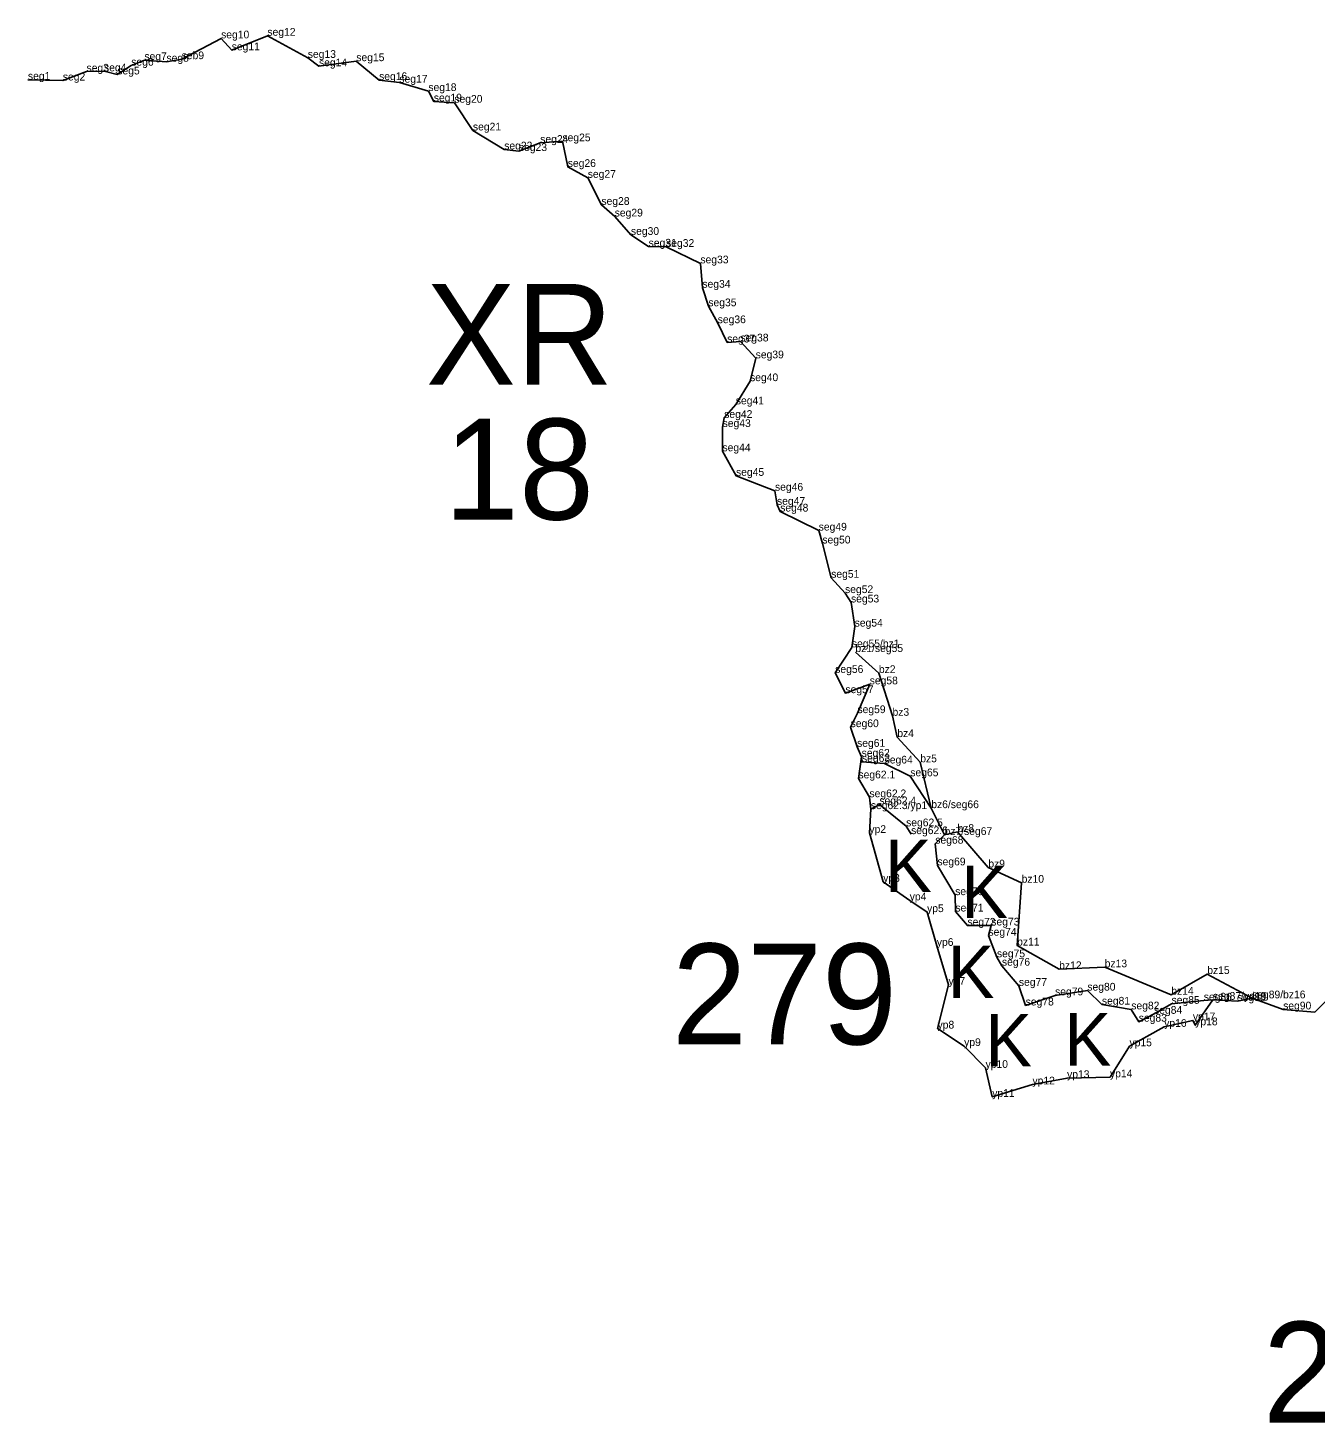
# Model space of a CAD drawing. Extents: x 2072529 to 2268796, y 436423 to 470406.
# Drawn here: x 2240745 to 2241579, y 439812 to 440717 of the extents above; entities that cross this region are included whole.
import ezdxf

# ---------------------------------------------------------------- set-up
doc = ezdxf.new("R2010")
doc.units = 0
for name, color, linetype in [('Default', 7, 'Continuous'), ('Exist Environmental Wetland Boundary Cogo Comment', 7, 'Continuous'), ('Exist Environmental Wetland Boundary Cogo Point CELL', 7, 'Continuous'), ('Exist Hydro Jurisdictional Stream or Body of Water NEU Mitigable Cogo Comment', 7, 'Continuous'), ('Old_Level_20', 7, 'Continuous'), ('Old_Level_52', 7, 'Continuous')]:
    doc.layers.add(name, color=color, linetype=linetype)

msp = doc.modelspace()

# ---------------------------------------------------------------- linework, layer by layer
at = {"layer": 'Old_Level_20'}
for p, q in [((2240900.59, 440712.1), (2240900.59, 440712.1)), ((2240870.61, 440710.41), (2240870.61, 440710.41)), ((2240877.46, 440702.68), (2240877.46, 440702.68)), ((2240812.4, 440692.72), (2240812.4, 440692.72)), ((2240820.91, 440696.34), (2240820.91, 440696.34)), ((2240835.21, 440695.28), (2240835.21, 440695.28)), ((2240845.05, 440696.92), (2240845.05, 440696.92)), ((2240926.76, 440697.76), (2240926.76, 440697.76)), ((2240958.18, 440695.63), (2240958.18, 440695.63)), ((2240745.46, 440683.58), (2240745.46, 440683.58)), ((2240783.43, 440688.86), (2240783.43, 440688.86)), ((2240794.77, 440689.05), (2240794.77, 440689.05)), ((2240803.35, 440687.04), (2240803.35, 440687.04)), ((2240934.01, 440692.29), (2240934.01, 440692.29)), ((2240768.08, 440683.09), (2240768.08, 440683.09)), ((2240972.96, 440683.39), (2240972.96, 440683.39)), ((2240986.1, 440681.7), (2240986.1, 440681.7)), ((2241004.88, 440676.28), (2241004.88, 440676.28)), ((2241008.39, 440669.53), (2241008.39, 440669.53)), ((2241021.69, 440668.7), (2241021.69, 440668.7)), ((2241033.73, 440650.71), (2241033.73, 440650.71)), ((2241054, 440638.41), (2241054, 440638.41)), ((2241077.34, 440642.67), (2241077.34, 440642.67)), ((2241091.72, 440643.72), (2241091.72, 440643.72)), ((2241063.51, 440637.41), (2241063.51, 440637.41)), ((2241095.19, 440627.08), (2241095.19, 440627.08)), ((2241108.12, 440620.04), (2241108.12, 440620.04)), ((2241116.98, 440602.51), (2241116.98, 440602.51)), ((2241125.58, 440594.97), (2241125.58, 440594.97)), ((2241136.1, 440583.04), (2241136.1, 440583.04)), ((2241147.55, 440575.46), (2241147.55, 440575.46)), ((2241158.87, 440575.28), (2241158.87, 440575.28)), ((2241181.1, 440564.6), (2241181.1, 440564.6)), ((2241182.39, 440548.78), (2241182.39, 440548.78)), ((2241186.24, 440536.8), (2241186.24, 440536.8)), ((2241192.31, 440525.82), (2241192.31, 440525.82)), ((2241198.43, 440513.33), (2241198.43, 440513.33)), ((2241207.02, 440513.98), (2241207.02, 440513.98)), ((2241216.9, 440503.05), (2241216.9, 440503.05)), ((2241213.27, 440488.25), (2241213.27, 440488.25)), ((2241204.04, 440473.22), (2241204.04, 440473.22)), ((2241195.49, 440458.54), (2241195.49, 440458.54)), ((2241196.53, 440464.43), (2241196.53, 440464.43)), ((2241195.39, 440442.82), (2241195.39, 440442.82)), ((2241204.17, 440426.87), (2241204.17, 440426.87)), ((2241229.41, 440417.26), (2241229.41, 440417.26)), ((2241230.72, 440408.11), (2241230.72, 440408.11)), ((2241232.79, 440403.75), (2241232.79, 440403.75)), ((2241257.72, 440391.43), (2241257.72, 440391.43)), ((2241260.12, 440383.05), (2241260.12, 440383.05)), ((2241265.82, 440360.85), (2241265.82, 440360.85)), ((2241274.8, 440350.9), (2241274.8, 440350.9)), ((2241278.67, 440344.84), (2241278.67, 440344.84)), ((2241281.02, 440329.2), (2241281.02, 440329.2)), ((2241279.21, 440315.74), (2241279.21, 440315.74)), ((2241281.51, 440312.72), (2241281.51, 440312.72)), ((2241268.43, 440299.17), (2241268.43, 440299.17)), ((2241296.71, 440299.1), (2241296.71, 440299.1)), ((2241275.06, 440286.05), (2241275.06, 440286.05)), ((2241290.77, 440291.78), (2241290.77, 440291.78)), ((2241282.83, 440273.11), (2241282.83, 440273.11)), ((2241305.55, 440271.4), (2241305.55, 440271.4)), ((2241278.42, 440264.03), (2241278.42, 440264.03)), ((2241282.59, 440251.27), (2241282.59, 440251.27)), ((2241308.65, 440257.59), (2241308.65, 440257.59)), ((2241285.54, 440244.89), (2241285.54, 440244.89)), ((2241285.76, 440241.46), (2241285.76, 440241.46)), ((2241300.42, 440240.47), (2241300.42, 440240.47)), ((2241323.52, 440241.26), (2241323.52, 440241.26)), ((2241317.07, 440232.2), (2241317.07, 440232.2)), ((2241283.48, 440230.81), (2241283.48, 440230.81)), ((2241290.61, 440218.6), (2241290.61, 440218.6)), ((2241297.04, 440213.96), (2241297.04, 440213.96)), ((2241291.52, 440210.9), (2241291.52, 440210.9)), ((2241330.65, 440211.53), (2241330.65, 440211.53)), ((2241330.65, 440211.53), (2241330.65, 440211.53)), ((2241290.57, 440195.44), (2241290.57, 440195.44)), ((2241314.36, 440199.77), (2241314.36, 440199.77)), ((2241347.6, 440196.12), (2241347.6, 440196.12)), ((2241317.58, 440194.69), (2241317.58, 440194.69)), ((2241333.25, 440188.5), (2241333.25, 440188.5)), ((2241339.26, 440194.15), (2241339.26, 440194.15)), ((2241339.26, 440194.15), (2241339.26, 440194.15)), ((2241334.64, 440174.46), (2241334.64, 440174.46)), ((2241367.6, 440173.08), (2241367.6, 440173.08)), ((2241299.52, 440163.78), (2241299.52, 440163.78)), ((2241389.18, 440163.21), (2241389.18, 440163.21)), ((2241316.69, 440151.78), (2241316.69, 440151.78)), ((2241346.14, 440155.15), (2241346.14, 440155.15)), ((2241327.93, 440144.15), (2241327.93, 440144.15)), ((2241346.29, 440144.54), (2241346.29, 440144.54)), ((2241354.1, 440135.38), (2241354.1, 440135.38)), ((2241369.55, 440135.48), (2241369.55, 440135.48)), ((2241367.69, 440128.9), (2241367.69, 440128.9)), ((2241334.25, 440122.27), (2241334.25, 440122.27)), ((2241373.19, 440114.85), (2241373.19, 440114.85)), ((2241386.29, 440122.5), (2241386.29, 440122.5)), ((2241376.42, 440109.43), (2241376.42, 440109.43)), ((2241413.51, 440107.19), (2241413.51, 440107.19)), ((2241442.98, 440108.39), (2241442.98, 440108.39)), ((2241341.85, 440097.04), (2241341.85, 440097.04)), ((2241387.41, 440096.36), (2241387.41, 440096.36)), ((2241509.42, 440104.04), (2241509.42, 440104.04)), ((2241410.86, 440090.21), (2241410.86, 440090.21)), ((2241431.76, 440093.29), (2241431.76, 440093.29)), ((2241486.13, 440090.61), (2241486.13, 440090.61)), ((2241507.18, 440086.84), (2241507.18, 440086.84)), ((2241513.12, 440087.33), (2241513.12, 440087.33)), ((2241513.12, 440087.33), (2241513.12, 440087.33)), ((2241529.06, 440086.49), (2241529.06, 440086.49)), ((2241538.49, 440088.28), (2241538.49, 440088.28)), ((2241538.49, 440088.28), (2241538.49, 440088.28)), ((2241391.79, 440083.64), (2241391.79, 440083.64)), ((2241441.19, 440084.2), (2241441.19, 440084.2)), ((2241460.21, 440081.1), (2241460.21, 440081.1)), ((2241474.98, 440078.25), (2241474.98, 440078.25)), ((2241486.3, 440084.74), (2241486.3, 440084.74)), ((2241558.6, 440081.08), (2241558.6, 440081.08)), ((2241579.17, 440079.38), (2241579.17, 440079.38)), ((2241334.73, 440068.7), (2241334.73, 440068.7)), ((2241465.06, 440073.15), (2241465.06, 440073.15)), ((2241481.53, 440069.8), (2241481.53, 440069.8)), ((2241500.12, 440074), (2241500.12, 440074)), ((2241501.66, 440070.84), (2241501.66, 440070.84)), ((2241351.94, 440057.37), (2241351.94, 440057.37)), ((2241459.06, 440057.21), (2241459.06, 440057.21)), ((2241365.82, 440043.17), (2241365.82, 440043.17)), ((2241396.19, 440032.47), (2241396.19, 440032.47)), ((2241418.63, 440036.6), (2241418.63, 440036.6)), ((2241446.44, 440037.09), (2241446.44, 440037.09)), ((2241370.15, 440024.41), (2241370.15, 440024.41))]:
    msp.add_line(p, q, dxfattribs=at)
for points in [[(2241281.51, 440312.72), (2241296.71, 440299.1), (2241305.55, 440271.4), (2241308.65, 440257.59), (2241323.52, 440241.26), (2241330.65, 440211.53)], [(2241513.12, 440087.33), (2241501.66, 440070.84), (2241500.12, 440074), (2241481.53, 440069.8), (2241459.06, 440057.21), (2241446.44, 440037.09), (2241418.63, 440036.6), (2241396.19, 440032.47), (2241370.15, 440024.41), (2241365.82, 440043.17), (2241351.94, 440057.37), (2241334.73, 440068.7), (2241341.85, 440097.04), (2241334.25, 440122.27), (2241327.93, 440144.15), (2241316.69, 440151.78), (2241299.52, 440163.78), (2241290.57, 440195.44), (2241291.52, 440210.9)], [(2241339.26, 440194.15), (2241347.6, 440196.12), (2241367.6, 440173.08), (2241389.18, 440163.21), (2241386.29, 440122.5), (2241413.51, 440107.19), (2241442.98, 440108.39), (2241486.13, 440090.61), (2241509.42, 440104.04), (2241538.49, 440088.28)]]:
    msp.add_lwpolyline(points, dxfattribs=at)
at = {"layer": 'Old_Level_52'}
for points in [[(2240745.46, 440683.58), (2240768.08, 440683.09), (2240783.43, 440688.86), (2240794.77, 440689.05), (2240803.35, 440687.04), (2240812.4, 440692.72), (2240820.91, 440696.34), (2240835.21, 440695.28), (2240845.05, 440696.92), (2240870.61, 440710.41), (2240877.46, 440702.68), (2240900.59, 440712.1), (2240926.76, 440697.76), (2240934.01, 440692.29), (2240958.18, 440695.63), (2240972.96, 440683.39), (2240986.1, 440681.7), (2241004.88, 440676.28), (2241008.39, 440669.53), (2241021.69, 440668.7)], [(2241021.69, 440668.7), (2241033.73, 440650.71), (2241054, 440638.41), (2241063.51, 440637.41), (2241077.34, 440642.67), (2241091.72, 440643.72), (2241095.19, 440627.08), (2241108.12, 440620.04), (2241116.98, 440602.51), (2241125.58, 440594.97), (2241136.1, 440583.04), (2241147.55, 440575.46), (2241158.87, 440575.28), (2241181.1, 440564.6), (2241182.39, 440548.78), (2241186.24, 440536.8), (2241192.31, 440525.82), (2241198.43, 440513.33), (2241207.02, 440513.98), (2241216.9, 440503.05), (2241213.27, 440488.25), (2241204.04, 440473.22), (2241196.53, 440464.43), (2241195.49, 440458.54), (2241195.39, 440442.82), (2241204.17, 440426.87), (2241229.41, 440417.26), (2241230.72, 440408.11), (2241232.79, 440403.75), (2241257.72, 440391.43), (2241260.12, 440383.05), (2241265.82, 440360.85), (2241274.8, 440350.9), (2241278.67, 440344.84), (2241281.02, 440329.2), (2241279.21, 440315.74), (2241268.43, 440299.17), (2241275.06, 440286.05), (2241290.77, 440291.78), (2241282.83, 440273.11), (2241278.42, 440264.03), (2241282.59, 440251.27), (2241285.54, 440244.89), (2241285.76, 440241.46)], [(2241285.54, 440244.89), (2241283.48, 440230.81), (2241290.61, 440218.6), (2241291.52, 440210.9), (2241297.04, 440213.96), (2241314.36, 440199.77), (2241317.58, 440194.69)], [(2241285.76, 440241.46), (2241300.42, 440240.47), (2241317.07, 440232.2), (2241330.65, 440211.53), (2241339.26, 440194.15), (2241333.25, 440188.5), (2241334.64, 440174.46), (2241346.14, 440155.15), (2241346.29, 440144.54), (2241354.1, 440135.38), (2241369.55, 440135.48), (2241367.69, 440128.9), (2241373.19, 440114.85), (2241376.42, 440109.43), (2241387.41, 440096.36), (2241391.79, 440083.64), (2241410.86, 440090.21), (2241431.76, 440093.29), (2241441.19, 440084.2), (2241460.21, 440081.1), (2241465.06, 440073.15), (2241474.98, 440078.25), (2241486.3, 440084.74), (2241507.18, 440086.84), (2241513.12, 440087.33), (2241529.06, 440086.49), (2241538.49, 440088.28), (2241558.6, 440081.08), (2241579.17, 440079.38), (2241588.56, 440088.74)]]:
    msp.add_lwpolyline(points, dxfattribs=at)

# ---------------------------------------------------------------- texts
at = {"layer": 'Default'}
for s, p in [('XR', (2241003.21, 440485.96)), ('18', (2241015, 440398.56)), ('279', (2241162.66, 440058.41)), ('281', (2241545.45, 439813.28))]:
    msp.add_text(s, height=65.34, dxfattribs=at).set_placement(p)
at = {"layer": 'Exist Environmental Wetland Boundary Cogo Comment'}
for s, p in [('bz1/seg55', (2241281.51, 440312.72)), ('bz2', (2241296.71, 440299.1)), ('bz3', (2241305.55, 440271.4)), ('bz4', (2241308.65, 440257.59)), ('bz5', (2241323.52, 440241.26)), ('bz6/seg66', (2241330.65, 440211.53)), ('yp2', (2241290.57, 440195.44)), ('bz8', (2241347.6, 440196.12)), ('bz9', (2241367.6, 440173.08)), ('yp3', (2241299.52, 440163.78)), ('bz10', (2241389.18, 440163.21)), ('yp4', (2241316.69, 440151.78)), ('yp5', (2241327.93, 440144.15)), ('yp6', (2241334.25, 440122.27)), ('bz11', (2241386.29, 440122.5)), ('bz13', (2241442.98, 440108.39)), ('bz12', (2241413.51, 440107.19)), ('bz15', (2241509.42, 440104.04)), ('yp7', (2241341.85, 440097.04)), ('bz14', (2241486.13, 440090.61)), ('yp17', (2241500.12, 440074)), ('yp8', (2241334.73, 440068.7)), ('yp16', (2241481.53, 440069.8)), ('yp18', (2241501.66, 440070.84)), ('yp9', (2241351.94, 440057.37)), ('yp15', (2241459.06, 440057.21)), ('yp10', (2241365.82, 440043.17)), ('yp13', (2241418.63, 440036.6)), ('yp14', (2241446.44, 440037.09)), ('yp12', (2241396.19, 440032.47)), ('yp11', (2241370.15, 440024.41))]:
    msp.add_text(s, height=5, dxfattribs=at).set_placement(p)
at = {"layer": 'Exist Environmental Wetland Boundary Cogo Point CELL'}
for p in [(2241300.62, 440157.2), (2241349.98, 440140.33), (2241341.23, 440088.47), (2241365.6, 440044.11), (2241416.83, 440044.74)]:
    msp.add_text('K', height=34, dxfattribs=at).set_placement(p)
at = {"layer": 'Exist Hydro Jurisdictional Stream or Body of Water NEU Mitigable Cogo Comment'}
for s, p in [('seg10', (2240870.61, 440710.41)), ('seg12', (2240900.59, 440712.1)), ('seb9', (2240845.05, 440696.92)), ('seg11', (2240877.46, 440702.68)), ('seg13', (2240926.76, 440697.76)), ('seg3', (2240783.43, 440688.86)), ('seg4', (2240794.77, 440689.05)), ('seg6', (2240812.4, 440692.72)), ('seg7', (2240820.91, 440696.34)), ('seg8', (2240835.21, 440695.28)), ('seg14', (2240934.01, 440692.29)), ('seg15', (2240958.18, 440695.63)), ('seg1', (2240745.46, 440683.58)), ('seg2', (2240768.08, 440683.09)), ('seg5', (2240803.35, 440687.04)), ('seg16', (2240972.96, 440683.39)), ('seg17', (2240986.1, 440681.7)), ('seg18', (2241004.88, 440676.28)), ('seg19', (2241008.39, 440669.53)), ('seg20', (2241021.69, 440668.7)), ('seg21', (2241033.73, 440650.71)), ('seg24', (2241077.34, 440642.67)), ('seg25', (2241091.72, 440643.72)), ('seg22', (2241054, 440638.41)), ('seg23', (2241063.51, 440637.41)), ('seg26', (2241095.19, 440627.08)), ('seg27', (2241108.12, 440620.04)), ('seg28', (2241116.98, 440602.51)), ('seg29', (2241125.58, 440594.97)), ('seg30', (2241136.1, 440583.04)), ('seg31', (2241147.55, 440575.46)), ('seg32', (2241158.87, 440575.28)), ('seg33', (2241181.1, 440564.6)), ('seg34', (2241182.39, 440548.78)), ('seg35', (2241186.24, 440536.8)), ('seg36', (2241192.31, 440525.82)), ('seg37', (2241198.43, 440513.33)), ('seg38', (2241207.02, 440513.98)), ('seg39', (2241216.9, 440503.05)), ('seg40', (2241213.27, 440488.25)), ('seg41', (2241204.04, 440473.22)), ('seg42', (2241196.53, 440464.43)), ('seg43', (2241195.49, 440458.54)), ('seg44', (2241195.39, 440442.82)), ('seg45', (2241204.17, 440426.87)), ('seg46', (2241229.41, 440417.26)), ('seg47', (2241230.72, 440408.11)), ('seg48', (2241232.79, 440403.75)), ('seg49', (2241257.72, 440391.43)), ('seg50', (2241260.12, 440383.05)), ('seg51', (2241265.82, 440360.85)), ('seg52', (2241274.8, 440350.9)), ('seg53', (2241278.67, 440344.84)), ('seg54', (2241281.02, 440329.2)), ('seg55/bz1', (2241279.21, 440315.74)), ('seg56', (2241268.43, 440299.17)), ('seg58', (2241290.77, 440291.78)), ('seg57', (2241275.06, 440286.05)), ('seg59', (2241282.83, 440273.11)), ('seg60', (2241278.42, 440264.03)), ('seg61', (2241282.59, 440251.27)), ('seg62', (2241285.54, 440244.89)), ('seg63', (2241285.76, 440241.46)), ('seg64', (2241300.42, 440240.47)), ('seg62.1', (2241283.48, 440230.81)), ('seg65', (2241317.07, 440232.2)), ('seg62.2', (2241290.61, 440218.6)), ('seg62.3/yp1', (2241291.52, 440210.9)), ('seg62.4', (2241297.04, 440213.96)), ('seg62.5', (2241314.36, 440199.77)), ('seg62.6', (2241317.58, 440194.69)), ('bz7/seg67', (2241339.26, 440194.15)), ('seg68', (2241333.25, 440188.5)), ('seg69', (2241334.64, 440174.46)), ('seg70', (2241346.14, 440155.15)), ('seg71', (2241346.29, 440144.54)), ('seg72', (2241354.1, 440135.38)), ('seg74', (2241367.69, 440128.9)), ('seg73', (2241369.55, 440135.48)), ('seg75', (2241373.19, 440114.85)), ('seg76', (2241376.42, 440109.43)), ('seg77', (2241387.41, 440096.36)), ('seg80', (2241431.76, 440093.29)), ('seg78', (2241391.79, 440083.64)), ('seg79', (2241410.86, 440090.21)), ('seg81', (2241441.19, 440084.2)), ('seg85', (2241486.3, 440084.74)), ('seg86', (2241507.18, 440086.84)), ('seg87/yd19', (2241513.12, 440087.33)), ('seg88', (2241529.06, 440086.49)), ('seg89/bz16', (2241538.49, 440088.28)), ('seg82', (2241460.21, 440081.1)), ('seg83', (2241465.06, 440073.15)), ('seg84', (2241474.98, 440078.25)), ('seg90', (2241558.6, 440081.08))]:
    msp.add_text(s, height=5, dxfattribs=at).set_placement(p)

doc.saveas('drawing.dxf')
